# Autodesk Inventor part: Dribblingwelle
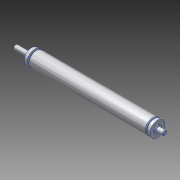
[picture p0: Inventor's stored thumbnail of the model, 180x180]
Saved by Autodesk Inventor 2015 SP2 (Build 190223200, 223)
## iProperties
Created: 2012-07
Part Number: Dribblingwelle
Material: Aluminium 6061
Document SubType Name: Modeling
Designer: rYan
Mass: 10.229 g
Surface Area: 21.1731 cm^2
Volume: 3.77453 cm^3
Density: 2.71 g/cm^3
Appearance: Aluminium - flach
Author: rYan
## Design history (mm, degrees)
sketch "Skizze1"
  geometry: L1 (-50, 0)-(-50, 1.5); L2 (-39.5, 1.5)-(-39.5, 2.5); L3 (50, 1.5)-(50, 0); L4 (50, 0)-(-50, 0); L5 (0, 6)-(0, -1) reference; L6 (-70, 0)-(70, 0) reference; L7 (-39.5, 1.5)-(-50, 1.5); L8 (50, 1.5)-(45.5, 1.5); L9 (45.5, 1.5)-(45.5, 2.5); L10 (-39.5, 2.5)-(-39, 2.5); L11 (-37, 5)-(-37, 3.5); L12 (-37, 3.5)-(-36.26, 3.5); L13 (-36.26, 3.5)-(-36.26, 5); L14 (-36.26, 5)-(42.26, 5); L15 (42.26, 5)-(42.26, 3.5); L16 (42.26, 3.5)-(43, 3.5); L17 (43, 3.5)-(43, 5); L18 (45, 2.5)-(45.5, 2.5); L19 (-37, 5)-(-39, 5); L20 (-39, 5)-(-39, 2.5); L21 (43, 5)-(45, 5); L22 (45, 5)-(45, 2.5); 1 further point
  constraints: 40 end point, 9 perpendicular, 6 collinear, 4 parallel, 3 horizontal, 2 point on line, 1 vertical, 1 other
  dimensions: "d21" = 3 diameter of L7 L4; "d23" = 10.5 distance of L2.start L1.end; "d24" = 4.5 distance of L3.start L8.end; "d25" = 5 diameter of L10 L4; "d27" = 10 diameter of L14 L4; "d28" = 0.74 distance of L11.end L12.end; "d29" = 0.5 distance of L2.end L10.end; "d30" = 10 diameter of L19 L4; "d31" = 7 diameter of L12 L4; "d32" = 0.5 distance of L18.start L9.end; "d33" = 85 distance between parallel lines of L2 L9; "d34" = 2 distance of L11.start L19.end
revolve "Umdrehung1" sketch "Skizze1" stored, may be unused: angle "d6" = 90 deg
chamfer "Fase1" distance "d35" = 0.5; stored, may be unused: second distance "d36" = 2, angle "d37" = 45 deg
chamfer "Fase2" distance "d38" = 0.5; stored, may be unused: second distance "d39" = 2, angle "d40" = 45 deg
node "Volumenkörper1"
